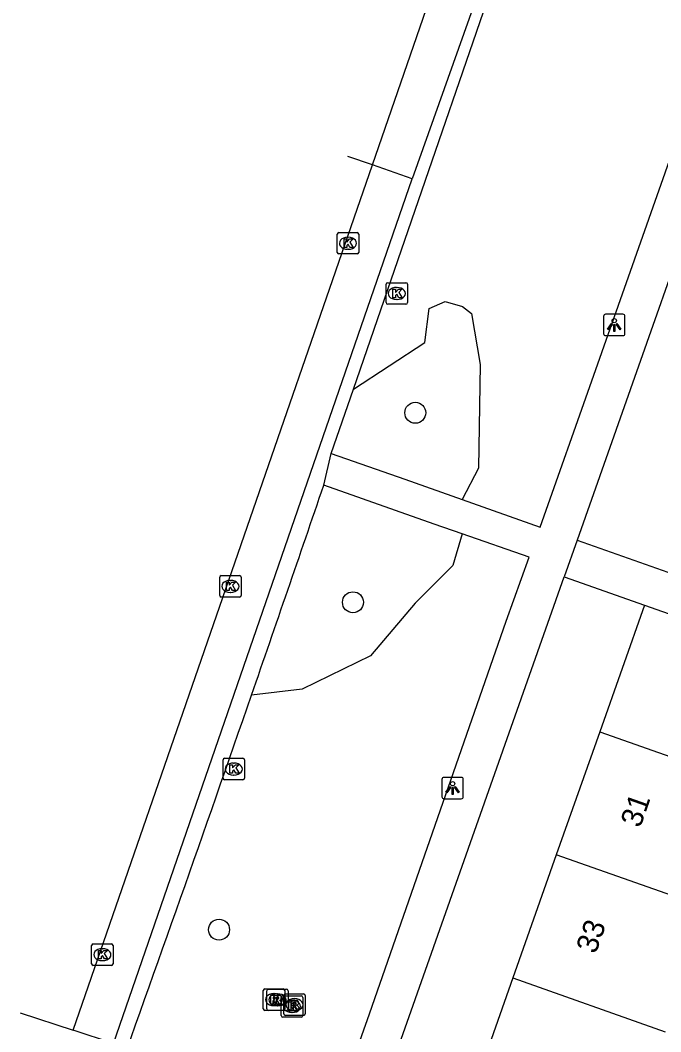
# Model space of a CAD drawing. Extents: x 163268 to 164360, y 381529 to 382285.
# Drawn here: x 163721.24 to 163751.14, y 381954.59 to 382001.8 of the extents above; entities that cross this region are included whole.
import ezdxf

# ---------------------------------------------------------------- set-up
doc = ezdxf.new("R2010")
doc.units = 0
for name, color, linetype in [('IMGEO_Boom', 7, 'Continuous'), ('IMGEO_Groenvoorziening', 7, 'Continuous'), ('IMGEO_Kolk', 7, 'Continuous'), ('IMGEO_Lichtpunt', 7, 'Continuous'), ('IMGEO_Pand', 7, 'Continuous'), ('IMGEO_Pand_nummerreeks', 7, 'Continuous'), ('IMGEO_Parkeervlak_open', 7, 'Continuous'), ('IMGEO_Rijbaan_lokaal_open', 7, 'Continuous'), ('IMGEO_Rioolput', 7, 'Continuous'), ('IMGEO_Voetpad_open', 7, 'Continuous')]:
    doc.layers.add(name, color=color, linetype=linetype)

msp = doc.modelspace()

# ---------------------------------------------------------------- linework, layer by layer
at = {"layer": 'IMGEO_Boom'}
for centre in [(163739.681, 381983.482), (163736.773, 381974.637), (163730.522, 381959.355)]:
    msp.add_circle(centre, 0.489, dxfattribs=at)
at = {"layer": 'IMGEO_Groenvoorziening'}
for points in [[(163736.791, 381984.576), (163740.131, 381986.758), (163740.336, 381988.355), (163741.073, 381988.682), (163741.892, 381988.437), (163742.301, 381988.109), (163742.711, 381985.734), (163742.629, 381980.902), (163741.871, 381979.435)], [(163741.875, 381977.831), (163741.441, 381976.356), (163739.681, 381974.596), (163737.592, 381972.139), (163734.398, 381970.583), (163732.04, 381970.304)]]:
    msp.add_lwpolyline(points, dxfattribs=at)
at = {"layer": 'IMGEO_Kolk'}
for p, q in [((163736.115, 381991.894), (163736.967, 381991.894)), ((163736.04, 381990.968), (163736.04, 381991.82)), ((163736.528, 381991.674), (163736.553, 381991.674)), ((163737.041, 381991.82), (163737.041, 381990.968)), ((163736.551, 381991.114), (163736.526, 381991.114)), ((163736.967, 381990.894), (163736.115, 381990.894)), ((163738.393, 381989.551), (163739.245, 381989.551)), ((163738.318, 381988.625), (163738.318, 381989.477)), ((163738.806, 381989.331), (163738.831, 381989.331)), ((163739.319, 381989.477), (163739.319, 381988.625)), ((163738.829, 381988.771), (163738.804, 381988.771)), ((163739.245, 381988.551), (163738.393, 381988.551)), ((163730.628, 381975.88), (163731.48, 381975.88)), ((163730.553, 381974.954), (163730.553, 381975.806)), ((163731.041, 381975.66), (163731.066, 381975.66)), ((163731.554, 381975.806), (163731.554, 381974.954)), ((163731.064, 381975.1), (163731.039, 381975.1)), ((163731.48, 381974.88), (163730.628, 381974.88)), ((163730.785, 381967.354), (163731.637, 381967.354)), ((163730.71, 381966.428), (163730.71, 381967.28)), ((163731.198, 381967.134), (163731.223, 381967.134)), ((163731.711, 381967.28), (163731.711, 381966.428)), ((163731.221, 381966.574), (163731.196, 381966.574)), ((163731.637, 381966.354), (163730.785, 381966.354)), ((163724.576, 381957.762), (163724.576, 381958.614)), ((163724.651, 381958.688), (163725.503, 381958.688)), ((163725.064, 381958.468), (163725.089, 381958.468)), ((163725.577, 381958.614), (163725.577, 381957.762)), ((163725.087, 381957.908), (163725.062, 381957.908)), ((163725.503, 381957.688), (163724.651, 381957.688))]:
    msp.add_line(p, q, dxfattribs=at)
for points in [[(163736.115, 381991.894), (163736.967, 381991.894)], [(163736.04, 381990.968), (163736.04, 381991.82)], [(163736.361, 381991.594), (163736.484, 381991.594), (163736.484, 381991.443), (163736.614, 381991.594), (163736.778, 381991.594), (163736.632, 381991.443), (163736.785, 381991.194), (163736.633, 381991.194), (163736.548, 381991.358), (163736.484, 381991.291), (163736.484, 381991.194), (163736.361, 381991.194), (163736.361, 381991.594)], [(163737.041, 381991.82), (163737.041, 381990.968)], [(163736.967, 381990.894), (163736.115, 381990.894)], [(163738.393, 381989.551), (163739.245, 381989.551)], [(163738.318, 381988.625), (163738.318, 381989.477)], [(163738.639, 381989.251), (163738.762, 381989.251), (163738.762, 381989.1), (163738.892, 381989.251), (163739.056, 381989.251), (163738.91, 381989.1), (163739.063, 381988.851), (163738.911, 381988.851), (163738.826, 381989.015), (163738.762, 381988.948), (163738.762, 381988.851), (163738.639, 381988.851), (163738.639, 381989.251)], [(163739.319, 381989.477), (163739.319, 381988.625)], [(163739.245, 381988.551), (163738.393, 381988.551)], [(163730.628, 381975.88), (163731.48, 381975.88)], [(163730.553, 381974.954), (163730.553, 381975.806)], [(163730.874, 381975.58), (163730.997, 381975.58), (163730.997, 381975.429), (163731.127, 381975.58), (163731.291, 381975.58), (163731.145, 381975.429), (163731.298, 381975.18), (163731.146, 381975.18), (163731.061, 381975.344), (163730.997, 381975.277), (163730.997, 381975.18), (163730.874, 381975.18), (163730.874, 381975.58)], [(163731.554, 381975.806), (163731.554, 381974.954)], [(163731.48, 381974.88), (163730.628, 381974.88)], [(163730.785, 381967.354), (163731.637, 381967.354)], [(163730.71, 381966.428), (163730.71, 381967.28)], [(163731.031, 381967.054), (163731.154, 381967.054), (163731.154, 381966.903), (163731.284, 381967.054), (163731.448, 381967.054), (163731.302, 381966.903), (163731.455, 381966.654), (163731.303, 381966.654), (163731.218, 381966.818), (163731.154, 381966.751), (163731.154, 381966.654), (163731.031, 381966.654), (163731.031, 381967.054)], [(163731.711, 381967.28), (163731.711, 381966.428)], [(163731.637, 381966.354), (163730.785, 381966.354)], [(163724.576, 381957.762), (163724.576, 381958.614)], [(163724.651, 381958.688), (163725.503, 381958.688)], [(163724.897, 381958.388), (163725.02, 381958.388), (163725.02, 381958.237), (163725.15, 381958.388), (163725.314, 381958.388), (163725.168, 381958.237), (163725.321, 381957.988), (163725.169, 381957.988), (163725.084, 381958.152), (163725.02, 381958.085), (163725.02, 381957.988), (163724.897, 381957.988), (163724.897, 381958.388)], [(163725.577, 381958.614), (163725.577, 381957.762)], [(163725.503, 381957.688), (163724.651, 381957.688)]]:
    msp.add_lwpolyline(points, dxfattribs=at)
for centre, start, end in [((163736.117, 381991.818), 91.552, 178.448), ((163736.117, 381991.818), 91.552, 178.448), ((163736.965, 381991.818), 1.552, 88.448), ((163736.965, 381991.818), 1.552, 88.448), ((163736.117, 381990.97), 181.552, 268.448), ((163736.117, 381990.97), 181.552, 268.448), ((163736.965, 381990.97), 271.552, 358.448), ((163736.965, 381990.97), 271.552, 358.448), ((163738.395, 381989.475), 91.552, 178.448), ((163738.395, 381989.475), 91.552, 178.448), ((163739.243, 381989.475), 1.552, 88.448), ((163739.243, 381989.475), 1.552, 88.448), ((163738.395, 381988.627), 181.552, 268.448), ((163738.395, 381988.627), 181.552, 268.448), ((163739.243, 381988.627), 271.552, 358.448), ((163739.243, 381988.627), 271.552, 358.448), ((163730.63, 381975.804), 91.552, 178.448), ((163730.63, 381975.804), 91.552, 178.448), ((163731.478, 381975.804), 1.552, 88.448), ((163731.478, 381975.804), 1.552, 88.448), ((163730.63, 381974.956), 181.552, 268.448), ((163730.63, 381974.956), 181.552, 268.448), ((163731.478, 381974.956), 271.552, 358.448), ((163731.478, 381974.956), 271.552, 358.448), ((163730.787, 381967.278), 91.552, 178.448), ((163730.787, 381967.278), 91.552, 178.448), ((163731.635, 381967.278), 1.552, 88.448), ((163731.635, 381967.278), 1.552, 88.448), ((163730.787, 381966.43), 181.552, 268.448), ((163730.787, 381966.43), 181.552, 268.448), ((163731.635, 381966.43), 271.552, 358.448), ((163731.635, 381966.43), 271.552, 358.448), ((163724.653, 381958.612), 91.552, 178.448), ((163724.653, 381958.612), 91.552, 178.448), ((163725.501, 381958.612), 1.552, 88.448), ((163725.501, 381958.612), 1.552, 88.448), ((163724.653, 381957.764), 181.552, 268.448), ((163724.653, 381957.764), 181.552, 268.448), ((163725.501, 381957.764), 271.552, 358.448), ((163725.501, 381957.764), 271.552, 358.448)]:
    msp.add_arc(centre, 0.0765, start, end, dxfattribs=at)
for centre, major_axis, ratio, start_param, end_param in [((163736.527, 381991.394), (-0.387, 0.002), 0.722429, 4.712389, 7.853982), ((163736.552, 381991.394), (-0.39, 0.002), 0.717154, 1.570796, 4.712389), ((163738.805, 381989.051), (-0.387, 0.002), 0.722429, 4.712389, 7.853982), ((163738.83, 381989.051), (-0.39, 0.002), 0.717154, 1.570796, 4.712389), ((163731.04, 381975.38), (-0.387, 0.002), 0.722429, 4.712389, 7.853982), ((163731.065, 381975.38), (-0.39, 0.002), 0.717154, 1.570796, 4.712389), ((163731.197, 381966.854), (-0.387, 0.002), 0.722429, 4.712389, 7.853982), ((163731.222, 381966.854), (-0.39, 0.002), 0.717154, 1.570796, 4.712389), ((163725.063, 381958.188), (-0.387, 0.002), 0.722429, 4.712389, 7.853982), ((163725.088, 381958.188), (-0.39, 0.002), 0.717154, 1.570796, 4.712389)]:
    msp.add_ellipse(centre, major_axis=major_axis, ratio=ratio, start_param=start_param, end_param=end_param, dxfattribs=at)
at = {"layer": 'IMGEO_Lichtpunt'}
for p, q in [((163748.47, 381987.983), (163748.47, 381987.176)), ((163748.47, 381987.983), (163748.47, 381987.176)), ((163749.372, 381988.078), (163748.564, 381988.078)), ((163749.372, 381988.078), (163748.564, 381988.078)), ((163749.466, 381987.176), (163749.466, 381987.983)), ((163749.466, 381987.176), (163749.466, 381987.983)), ((163748.564, 381987.082), (163749.372, 381987.082)), ((163748.564, 381987.082), (163749.372, 381987.082)), ((163741.827, 381966.463), (163741.019, 381966.463)), ((163741.827, 381966.463), (163741.019, 381966.463)), ((163740.925, 381966.368), (163740.925, 381965.561)), ((163740.925, 381966.368), (163740.925, 381965.561)), ((163741.921, 381965.561), (163741.921, 381966.368)), ((163741.921, 381965.561), (163741.921, 381966.368)), ((163741.019, 381965.467), (163741.827, 381965.467)), ((163741.019, 381965.467), (163741.827, 381965.467))]:
    msp.add_line(p, q, dxfattribs=at)
for points in [[(163748.844, 381987.647), (163748.883, 381987.619), (163748.695, 381987.357), (163748.657, 381987.384), (163748.844, 381987.647)], [(163749.056, 381987.619), (163749.094, 381987.646), (163749.281, 381987.384), (163749.242, 381987.356), (163749.056, 381987.619)], [(163748.946, 381987.599), (163748.993, 381987.599), (163748.993, 381987.277), (163748.946, 381987.277), (163748.946, 381987.599)], [(163741.299, 381966.032), (163741.338, 381966.004), (163741.15, 381965.742), (163741.112, 381965.769), (163741.299, 381966.032)], [(163741.401, 381965.984), (163741.448, 381965.984), (163741.448, 381965.662), (163741.401, 381965.662), (163741.401, 381965.984)], [(163741.511, 381966.004), (163741.549, 381966.031), (163741.736, 381965.769), (163741.697, 381965.741), (163741.511, 381966.004)]]:
    msp.add_lwpolyline(points, dxfattribs=at)
for centre in [(163748.969, 381987.781), (163741.424, 381966.166)]:
    msp.add_circle(centre, 0.0994, dxfattribs=at)
for centre, start, end in [((163748.564, 381987.983), 90, 180), ((163748.564, 381987.983), 90, 180), ((163749.372, 381987.983), 0, 90), ((163749.372, 381987.983), 0, 90), ((163748.564, 381987.176), 180, 270), ((163748.564, 381987.176), 180, 270), ((163749.372, 381987.176), 270, 0), ((163749.372, 381987.176), 270, 360), ((163741.019, 381966.368), 90, 180), ((163741.019, 381966.368), 90, 180), ((163741.827, 381966.368), 0, 90), ((163741.827, 381966.368), 0, 90), ((163741.019, 381965.561), 180, 270), ((163741.019, 381965.561), 180, 270), ((163741.827, 381965.561), 270, 0), ((163741.827, 381965.561), 270, 360)]:
    msp.add_arc(centre, 0.0946, start, end, dxfattribs=at)
at = {"layer": 'IMGEO_Pand'}
for points in [[(163750.374, 381974.5), (163748.29, 381968.588)], [(163750.374, 381974.5), (163755.103, 381972.832), (163757.486, 381971.991)], [(163748.29, 381968.588), (163746.264, 381962.845)], [(163748.29, 381968.588), (163755.402, 381966.08)], [(163746.264, 381962.845), (163744.239, 381957.101)], [(163753.377, 381960.336), (163746.264, 381962.845)], [(163744.239, 381957.101), (163742.214, 381951.358)], [(163744.239, 381957.101), (163751.351, 381954.593)]]:
    msp.add_lwpolyline(points, dxfattribs=at)
at = {"layer": 'IMGEO_Parkeervlak_open'}
msp.add_lwpolyline([(163739.53, 381994.406), (163737.681, 381995.055)], dxfattribs=at)
at = {"layer": 'IMGEO_Rijbaan_lokaal_open'}
for points in [[(163737.681, 381995.055), (163743.599, 382012.188)], [(163737.681, 381995.055), (163736.527, 381995.448)], [(163723.722, 381954.666), (163737.681, 381995.055)], [(163721.244, 381955.481), (163723.722, 381954.666)], [(163725.601, 381954.038), (163723.722, 381954.666)]]:
    msp.add_lwpolyline(points, dxfattribs=at)
at = {"layer": 'IMGEO_Rioolput'}
for p, q in [((163732.588, 381955.664), (163732.588, 381956.516)), ((163732.663, 381956.59), (163733.515, 381956.59)), ((163732.746, 381955.655), (163732.746, 381956.507)), ((163732.821, 381956.581), (163733.673, 381956.581)), ((163733.589, 381956.516), (163733.589, 381955.664)), ((163733.747, 381956.507), (163733.747, 381955.655)), ((163733.076, 381956.37), (163733.101, 381956.37)), ((163733.234, 381956.361), (163733.259, 381956.361)), ((163733.425, 381955.344), (163733.425, 381956.196)), ((163733.5, 381956.27), (163734.352, 381956.27)), ((163733.543, 381955.429), (163733.543, 381956.281)), ((163733.618, 381956.355), (163734.47, 381956.355)), ((163733.913, 381956.05), (163733.938, 381956.05)), ((163734.031, 381956.135), (163734.056, 381956.135)), ((163734.426, 381956.196), (163734.426, 381955.344)), ((163734.544, 381956.281), (163734.544, 381955.429)), ((163733.515, 381955.59), (163732.663, 381955.59)), ((163733.673, 381955.581), (163732.821, 381955.581)), ((163733.099, 381955.81), (163733.074, 381955.81)), ((163733.257, 381955.801), (163733.232, 381955.801)), ((163734.054, 381955.575), (163734.029, 381955.575)), ((163734.352, 381955.27), (163733.5, 381955.27)), ((163734.47, 381955.355), (163733.618, 381955.355)), ((163733.936, 381955.49), (163733.911, 381955.49))]:
    msp.add_line(p, q, dxfattribs=at)
for points in [[(163732.588, 381955.664), (163732.588, 381956.516)], [(163732.663, 381956.59), (163733.515, 381956.59)], [(163732.746, 381955.655), (163732.746, 381956.507)], [(163732.821, 381956.581), (163733.673, 381956.581)], [(163733.589, 381956.516), (163733.589, 381955.664)], [(163733.747, 381956.507), (163733.747, 381955.655)], [(163733.177, 381956.288), (163732.925, 381956.29), (163732.925, 381955.89)], [(163732.925, 381955.89), (163733.049, 381955.89), (163733.049, 381956.052), (163733.06, 381956.052)], [(163733.103, 381956.209), (163733.049, 381956.209), (163733.049, 381956.128)], [(163733.049, 381956.128), (163733.101, 381956.128)], [(163733.335, 381956.279), (163733.083, 381956.281), (163733.083, 381955.881)], [(163733.083, 381955.881), (163733.207, 381955.881), (163733.207, 381956.043), (163733.218, 381956.043)], [(163733.107, 381956.023), (163733.178, 381955.89), (163733.318, 381955.89), (163733.253, 381956.016)], [(163733.261, 381956.2), (163733.207, 381956.2), (163733.207, 381956.119)], [(163733.207, 381956.119), (163733.259, 381956.119)], [(163733.265, 381956.014), (163733.336, 381955.881), (163733.476, 381955.881), (163733.411, 381956.007)], [(163733.425, 381955.344), (163733.425, 381956.196)], [(163733.5, 381956.27), (163734.352, 381956.27)], [(163733.543, 381955.429), (163733.543, 381956.281)], [(163733.618, 381956.355), (163734.47, 381956.355)], [(163734.132, 381956.053), (163733.88, 381956.055), (163733.88, 381955.655)], [(163734.426, 381956.196), (163734.426, 381955.344)], [(163734.544, 381956.281), (163734.544, 381955.429)], [(163733.515, 381955.59), (163732.663, 381955.59)], [(163733.673, 381955.581), (163732.821, 381955.581)], [(163734.014, 381955.968), (163733.762, 381955.97), (163733.762, 381955.57)], [(163733.762, 381955.57), (163733.886, 381955.57), (163733.886, 381955.732), (163733.897, 381955.732)], [(163733.88, 381955.655), (163734.004, 381955.655), (163734.004, 381955.817), (163734.015, 381955.817)], [(163733.94, 381955.889), (163733.886, 381955.889), (163733.886, 381955.808)], [(163733.886, 381955.808), (163733.938, 381955.808)], [(163733.944, 381955.703), (163734.015, 381955.57), (163734.155, 381955.57), (163734.09, 381955.696)], [(163734.058, 381955.974), (163734.004, 381955.974), (163734.004, 381955.893)], [(163734.004, 381955.893), (163734.056, 381955.893)], [(163734.062, 381955.788), (163734.133, 381955.655), (163734.273, 381955.655), (163734.208, 381955.781)], [(163734.352, 381955.27), (163733.5, 381955.27)], [(163734.47, 381955.355), (163733.618, 381955.355)]]:
    msp.add_lwpolyline(points, dxfattribs=at)
for centre, radius, start, end in [((163732.665, 381956.514), 0.0765, 91.552, 178.448), ((163732.665, 381956.514), 0.0765, 91.552, 178.448), ((163732.823, 381956.505), 0.0765, 91.552, 178.448), ((163732.823, 381956.505), 0.0765, 91.552, 178.448), ((163733.513, 381956.514), 0.0765, 1.552, 88.448), ((163733.513, 381956.514), 0.0765, 1.552, 88.448), ((163733.671, 381956.505), 0.0765, 1.552, 88.448), ((163733.671, 381956.505), 0.0765, 1.552, 88.448), ((163733.059, 381955.999), 0.0533, 26.0293, 88.6989), ((163733.085, 381956.317), 0.19, 274.7715, 282.9687), ((163733.109, 381956.113), 0.0964, 77.0061, 93.1865), ((163733.123, 381956.17), 0.0378, 276.6634, 79.6772), ((163733.176, 381956.178), 0.109, 350.3612, 89.416), ((163733.174, 381956.178), 0.112, 277.5842, 350.9817), ((163733.158, 381955.963), 0.108, 29.5134, 73.7905), ((163733.217, 381955.99), 0.0533, 26.0293, 88.6989), ((163733.243, 381956.308), 0.19, 274.7715, 282.9687), ((163733.267, 381956.104), 0.0964, 77.0061, 93.1865), ((163733.281, 381956.161), 0.0378, 276.6634, 79.6772), ((163733.334, 381956.169), 0.109, 350.3612, 89.416), ((163733.332, 381956.169), 0.112, 277.5842, 350.9817), ((163733.316, 381955.954), 0.108, 29.5134, 73.7905), ((163733.502, 381956.194), 0.0765, 91.552, 178.448), ((163733.502, 381956.194), 0.0765, 91.552, 178.448), ((163733.62, 381956.279), 0.0765, 91.552, 178.448), ((163733.62, 381956.279), 0.0765, 91.552, 178.448), ((163734.131, 381955.943), 0.109, 350.3612, 89.416), ((163734.35, 381956.194), 0.0765, 1.552, 88.448), ((163734.35, 381956.194), 0.0765, 1.552, 88.448), ((163734.468, 381956.279), 0.0765, 1.552, 88.448), ((163734.468, 381956.279), 0.0765, 1.552, 88.448), ((163732.665, 381955.666), 0.0765, 181.552, 268.448), ((163732.665, 381955.666), 0.0765, 181.552, 268.448), ((163732.823, 381955.657), 0.0765, 181.552, 268.448), ((163732.823, 381955.657), 0.0765, 181.552, 268.448), ((163733.513, 381955.666), 0.0765, 271.552, 358.448), ((163733.513, 381955.666), 0.0765, 271.552, 358.448), ((163733.671, 381955.657), 0.0765, 271.552, 358.448), ((163733.671, 381955.657), 0.0765, 271.552, 358.448), ((163733.896, 381955.679), 0.0533, 26.0293, 88.6989), ((163733.922, 381955.997), 0.19, 274.7715, 282.9687), ((163733.946, 381955.793), 0.0964, 77.0061, 93.1865), ((163733.96, 381955.85), 0.0378, 276.6634, 79.6772), ((163734.013, 381955.858), 0.109, 350.3612, 89.416), ((163734.014, 381955.764), 0.0533, 26.0293, 88.6989), ((163734.011, 381955.858), 0.112, 277.5842, 350.9817), ((163733.995, 381955.643), 0.108, 29.5134, 73.7905), ((163734.04, 381956.082), 0.19, 274.7715, 282.9687), ((163734.064, 381955.878), 0.0964, 77.0061, 93.1865), ((163734.078, 381955.935), 0.0378, 276.6634, 79.6772), ((163734.129, 381955.943), 0.112, 277.5842, 350.9817), ((163734.113, 381955.728), 0.108, 29.5134, 73.7905), ((163733.502, 381955.346), 0.0765, 181.552, 268.448), ((163733.502, 381955.346), 0.0765, 181.552, 268.448), ((163733.62, 381955.431), 0.0765, 181.552, 268.448), ((163733.62, 381955.431), 0.0765, 181.552, 268.448), ((163734.35, 381955.346), 0.0765, 271.552, 358.448), ((163734.35, 381955.346), 0.0765, 271.552, 358.448), ((163734.468, 381955.431), 0.0765, 271.552, 358.448), ((163734.468, 381955.431), 0.0765, 271.552, 358.448)]:
    msp.add_arc(centre, radius, start, end, dxfattribs=at)
for centre, major_axis, ratio, start_param, end_param in [((163733.075, 381956.09), (-0.387, 0.002), 0.722429, 4.712389, 7.853982), ((163733.233, 381956.081), (-0.387, 0.002), 0.722429, 4.712389, 7.853982), ((163733.1, 381956.09), (-0.39, 0.002), 0.717154, 1.570796, 4.712389), ((163733.258, 381956.081), (-0.39, 0.002), 0.717154, 1.570796, 4.712389), ((163733.912, 381955.77), (-0.387, 0.002), 0.722429, 4.712389, 7.853982), ((163734.03, 381955.855), (-0.387, 0.002), 0.722429, 4.712389, 7.853982), ((163733.937, 381955.77), (-0.39, 0.002), 0.717154, 1.570796, 4.712389), ((163734.055, 381955.855), (-0.39, 0.002), 0.717154, 1.570796, 4.712389)]:
    msp.add_ellipse(centre, major_axis=major_axis, ratio=ratio, start_param=start_param, end_param=end_param, dxfattribs=at)
at = {"layer": 'IMGEO_Voetpad_open'}
for points in [[(163743.599, 382012.188), (163745.601, 382011.478), (163739.53, 381994.406)], [(163741.871, 381979.435), (163745.511, 381978.139), (163748.016, 381985.237), (163756.217, 382008.513), (163756.65, 382009.665)], [(163736.791, 381984.576), (163742.872, 382002.193), (163742.89, 382002.246)], [(163755.73, 382001.61), (163755.162, 382000), (163747.239, 381977.53)], [(163725.601, 381954.038), (163739.53, 381994.406)], [(163735.758, 381981.582), (163736.791, 381984.576)], [(163735.409, 381980.104), (163735.758, 381981.582)], [(163735.758, 381981.582), (163739.19, 381980.389), (163741.871, 381979.435)], [(163741.875, 381977.831), (163740.57, 381978.29), (163735.409, 381980.104)], [(163725.359, 381951.368), (163730.374, 381949.623), (163734.938, 381948.036), (163737.539, 381955.42), (163743.927, 381973.755), (163744.994, 381976.735), (163741.875, 381977.831)], [(163747.239, 381977.53), (163746.635, 381975.818)], [(163747.239, 381977.53), (163768.921, 381969.884), (163769.139, 381970.504), (163770.166, 381973.463)], [(163726.266, 381918.05), (163746.635, 381975.818)], [(163746.635, 381975.818), (163750.374, 381974.5)]]:
    msp.add_lwpolyline(points, dxfattribs=at)
for centre, radius, start, end in [((161866.086, 382617.252), 1974.924, 340.877962, 341.178608), ((161979.343, 382578.044), 1855.073, 340.25604, 340.876236)]:
    msp.add_arc(centre, radius, start, end, dxfattribs=at)

# ---------------------------------------------------------------- texts
at = {"layer": 'IMGEO_Pand_nummerreeks'}
for s, p in [('31', (163750.175, 381964.071)), ('33', (163748.101, 381958.187))]:
    msp.add_text(s, height=1, rotation=70.5777, dxfattribs=at).set_placement(p)

doc.saveas('drawing.dxf')
